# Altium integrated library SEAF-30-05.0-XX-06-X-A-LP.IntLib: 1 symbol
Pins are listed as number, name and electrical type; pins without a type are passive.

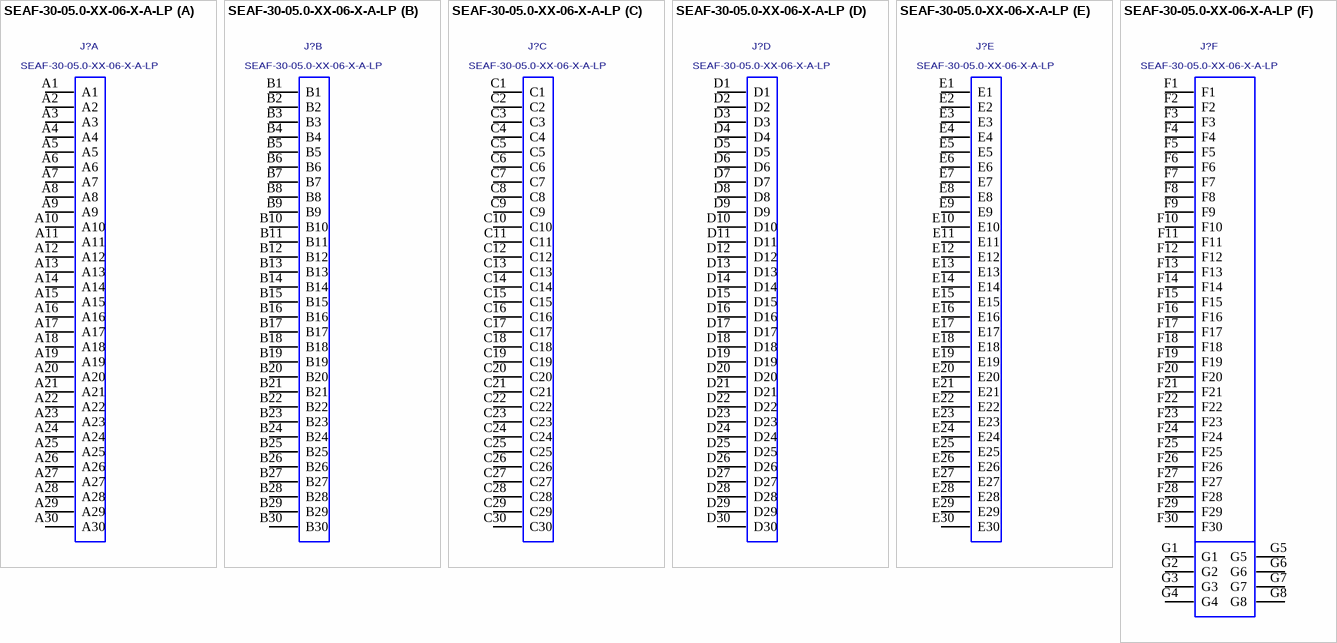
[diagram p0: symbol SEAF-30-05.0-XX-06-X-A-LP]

## SEAF-30-05.0-XX-06-X-A-LP
designator J?
Socket Array Assembly, Surface Mount With -LP Option, 0.050" Pitch, 180 Pins.; MANUFACTURER: SAMTEC
footprint SEAF-30-05.0-XX-06-X-A-LP
part A pins: A1, A2, A3, A4, A5, A6, A7, A8, A9, A10, A11, A12, A13, A14, A15, A16, A17, A18, A19, A20, A21, A22, A23, A24, A25, A26, A27, A28, A29, A30
part B pins: B1, B2, B3, B4, B5, B6, B7, B8, B9, B10, B11, B12, B13, B14, B15, B16, B17, B18, B19, B20, B21, B22, B23, B24, B25, B26, B27, B28, B29, B30
part C pins: C1, C2, C3, C4, C5, C6, C7, C8, C9, C10, C11, C12, C13, C14, C15, C16, C17, C18, C19, C20, C21, C22, C23, C24, C25, C26, C27, C28, C29, C30
part D pins: D1, D2, D3, D4, D5, D6, D7, D8, D9, D10, D11, D12, D13, D14, D15, D16, D17, D18, D19, D20, D21, D22, D23, D24, D25, D26, D27, D28, D29, D30
part E pins: E1, E2, E3, E4, E5, E6, E7, E8, E9, E10, E11, E12, E13, E14, E15, E16, E17, E18, E19, E20, E21, E22, E23, E24, E25, E26, E27, E28, E29, E30
part F pins: F1, F2, F3, F4, F5, F6, F7, F8, F9, F10, F11, F12, F13, F14, F15, F16, F17, F18, F19, F20, F21, F22, F23, F24, F25, F26, F27, F28, F29, F30, G1, G2, G3, G4, G5, G6, G7, G8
